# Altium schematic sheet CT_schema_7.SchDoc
size 274 x 160 mm
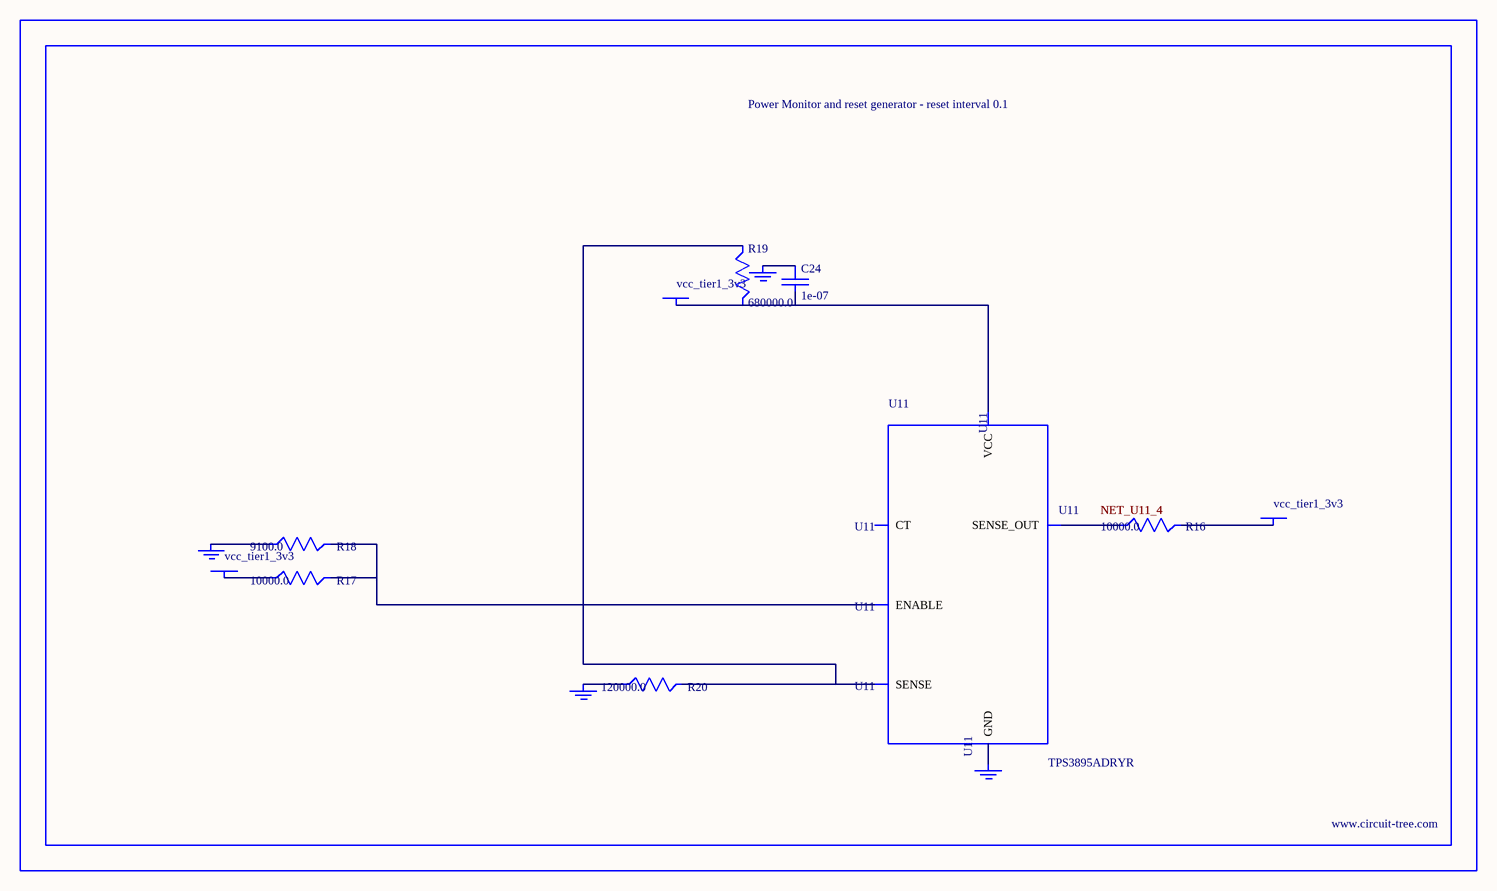
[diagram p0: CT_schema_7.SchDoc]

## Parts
BORDER6  (no value)
C24  1e-07  [C0402]
GND_INSTANCE_6_0  (no value)
GND_INSTANCE_6_1  (no value)
GND_INSTANCE_6_2  (no value)
GND_INSTANCE_6_3  (no value)
POWER_INSTANCE_6_0  vcc_tier1_3v3
POWER_INSTANCE_6_1  vcc_tier1_3v3
POWER_INSTANCE_6_2  vcc_tier1_3v3
R16  10000.0  [R0603]
R17  10000.0  [R0603]
R18  9100.0  [R0603]
R19  680000.0  [R0603]
R20  120000.0  [R0603]
U11  TPS3895ADRYR  [SON-6]

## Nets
NetC24_1: C24.1 GND_INSTANCE_6_2.0(GND)
NetC24_2: C24.2 POWER_INSTANCE_6_2.0(PWR) R19.2 U11.6(VCC)
NetGND_INSTANCE_6_0_0: GND_INSTANCE_6_0.0(GND) R18.1
NetGND_INSTANCE_6_1_0: GND_INSTANCE_6_1.0(GND) R20.1
NetGND_INSTANCE_6_3_0: GND_INSTANCE_6_3.0(GND) U11.2(GND)
NetPOWER_INSTANCE_6_0_0: POWER_INSTANCE_6_0.0(PWR) R17.1
NetPOWER_INSTANCE_6_1_0: POWER_INSTANCE_6_1.0(PWR) R16.2
NetR16_1: R16.1 U11.4(SENSE_OUT)
NetR17_2: R17.2 R18.2 U11.1(ENABLE)
NetR19_1: R19.1 R20.2 U11.3(SENSE)

Not connected (* = marked no-connect by the designer): U11 5(CT)

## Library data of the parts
BORDER6 = BORDER_PAGE6
C24 = C0402C104K3RACTU
GND_INSTANCE_6_0-GND_INSTANCE_6_3 = GND
POWER_INSTANCE_6_0-POWER_INSTANCE_6_2 = PWR
R16 R17 = RC0603JR-0710KL
R18 = RC0603JR-079K1L
R19 = RC0603JR-07680KL
R20 = RC0603JR-07120KL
